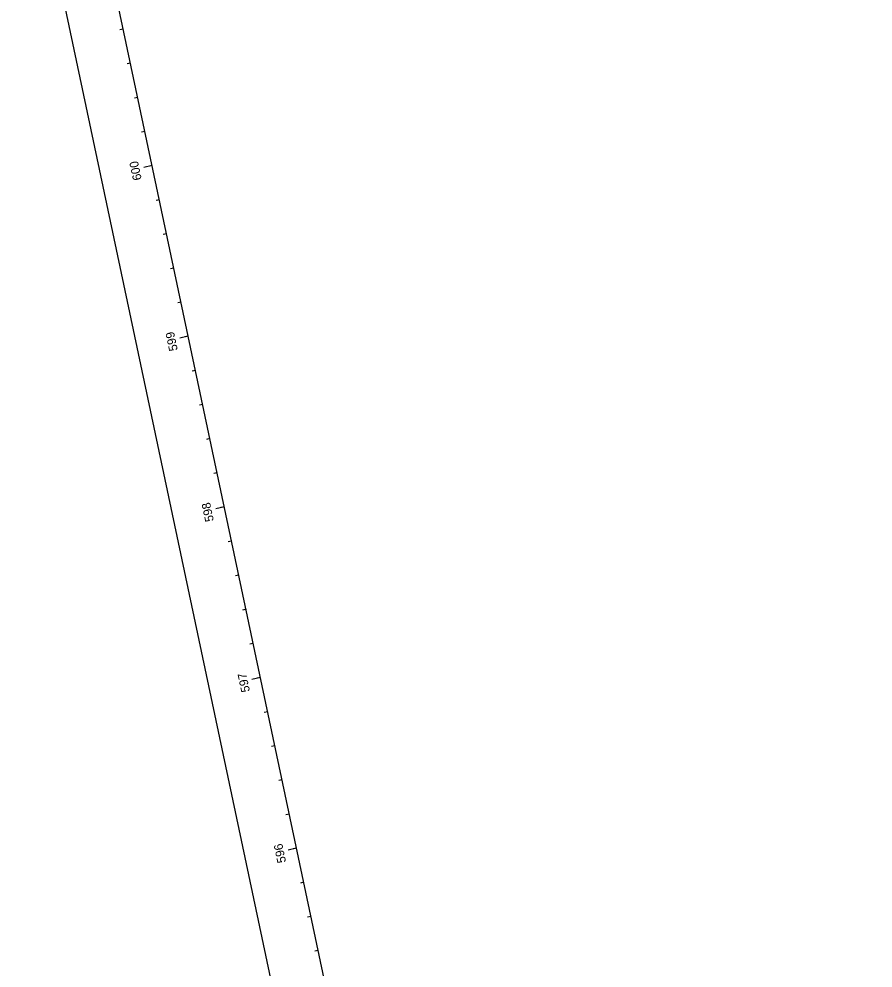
# Model space of a CAD drawing. Extents: x 2003883 to 2007688, y 399149 to 412300.
# Drawn here: x 2005065 to 2005555, y 406834 to 407378 of the extents above; entities that cross this region are included whole.
import ezdxf

# ---------------------------------------------------------------- set-up
doc = ezdxf.new("R2010")
doc.units = 0
for name, color, linetype in [('BaselineSurvey', 7, 'Continuous'), ('ConstLines', 7, 'Continuous'), ('Default', 7, 'Continuous'), ('TextAlgnStation100', 7, 'Continuous'), ('TextAlgnStation1000', 7, 'Continuous'), ('TextAlgnStation500', 7, 'Continuous'), ('TextAlgnStation5000', 7, 'Continuous'), ('TextAlgnTicks100', 7, 'Continuous'), ('TextAlgnTicks1000', 7, 'Continuous'), ('TextAlgnTicks500', 7, 'Continuous'), ('TextAlgnTicks5000', 7, 'Continuous')]:
    doc.layers.add(name, color=color, linetype=linetype)

msp = doc.modelspace()

# ---------------------------------------------------------------- linework, layer by layer
at = {"layer": 'BaselineSurvey'}
msp.add_line((2006223.92, 402174.38), (2005094.48, 407516.05), dxfattribs=at)
at = {"layer": 'ConstLines'}
msp.add_line((2006194.57, 402168.18), (2005065.13, 407509.84), dxfattribs=at)
at = {"layer": 'Default'}
msp.add_line((2006223.92, 402174.38), (2005094.48, 407516.05), dxfattribs=at)
at = {"layer": 'TextAlgnTicks100'}
for p, q in [((2005124.93, 407372.01), (2005122.98, 407371.6)), ((2005129.07, 407352.45), (2005127.11, 407352.03)), ((2005133.21, 407332.88), (2005131.25, 407332.46)), ((2005137.35, 407313.31), (2005135.39, 407312.9)), ((2005141.48, 407293.74), (2005136.59, 407292.71)), ((2005145.62, 407274.18), (2005143.66, 407273.76)), ((2005149.76, 407254.61), (2005147.8, 407254.2)), ((2005153.89, 407235.04), (2005151.94, 407234.63)), ((2005158.03, 407215.47), (2005156.08, 407215.06)), ((2005162.17, 407195.91), (2005157.28, 407194.87)), ((2005166.31, 407176.34), (2005164.35, 407175.93)), ((2005170.44, 407156.77), (2005168.49, 407156.36)), ((2005174.58, 407137.2), (2005172.62, 407136.79)), ((2005178.72, 407117.64), (2005176.76, 407117.22)), ((2005182.86, 407098.07), (2005177.96, 407097.04)), ((2005186.99, 407078.5), (2005185.04, 407078.09)), ((2005191.13, 407058.93), (2005189.17, 407058.52)), ((2005195.27, 407039.37), (2005193.31, 407038.95)), ((2005199.41, 407019.8), (2005197.45, 407019.39)), ((2005203.54, 407000.23), (2005198.65, 406999.2)), ((2005207.68, 406980.67), (2005205.72, 406980.25)), ((2005211.82, 406961.1), (2005209.86, 406960.68)), ((2005215.95, 406941.53), (2005214, 406941.12)), ((2005220.09, 406921.96), (2005218.14, 406921.55)), ((2005224.23, 406902.4), (2005219.34, 406901.36)), ((2005228.37, 406882.83), (2005226.41, 406882.41)), ((2005232.5, 406863.26), (2005230.55, 406862.85)), ((2005236.64, 406843.69), (2005234.68, 406843.28))]:
    msp.add_line(p, q, dxfattribs=at)
at = {"layer": 'TextAlgnTicks1000'}
for p, q in [((2005141.48, 407293.74), (2005136.59, 407292.71)), ((2005182.86, 407098.07), (2005180.9, 407097.66)), ((2005224.23, 406902.4), (2005222.27, 406901.98))]:
    msp.add_line(p, q, dxfattribs=at)
at = {"layer": 'TextAlgnTicks500'}
for p, q in [((2005141.48, 407293.74), (2005136.59, 407292.71)), ((2005162.17, 407195.91), (2005160.21, 407195.49)), ((2005182.86, 407098.07), (2005180.9, 407097.66)), ((2005203.54, 407000.23), (2005201.59, 406999.82)), ((2005224.23, 406902.4), (2005222.27, 406901.98))]:
    msp.add_line(p, q, dxfattribs=at)
at = {"layer": 'TextAlgnTicks5000'}
msp.add_line((2005141.48, 407293.74), (2005136.59, 407292.71), dxfattribs=at)

# ---------------------------------------------------------------- texts
at = {"layer": 'TextAlgnStation100'}
for s, p in [('600', (2005135.49, 407285.84)), ('599', (2005156.18, 407187.99)), ('598', (2005176.87, 407090.11)), ('597', (2005197.54, 406992.37)), ('596', (2005218.24, 406894.48))]:
    msp.add_text(s, height=4.98, rotation=101.9388, dxfattribs=at).set_placement(p)
at = {"layer": 'TextAlgnStation1000'}
msp.add_text('600', height=4.98, rotation=101.9388, dxfattribs=at).set_placement((2005135.49, 407285.84))
at = {"layer": 'TextAlgnStation500'}
msp.add_text('600', height=4.98, rotation=101.9388, dxfattribs=at).set_placement((2005135.49, 407285.84))
at = {"layer": 'TextAlgnStation5000'}
msp.add_text('600', height=4.98, rotation=101.9388, dxfattribs=at).set_placement((2005135.49, 407285.84))

doc.saveas('drawing.dxf')
